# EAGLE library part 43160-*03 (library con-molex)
SDA-43160 Connector Source: http://www.molex.com/pdm_docs/sd/431601306_sd.pdf
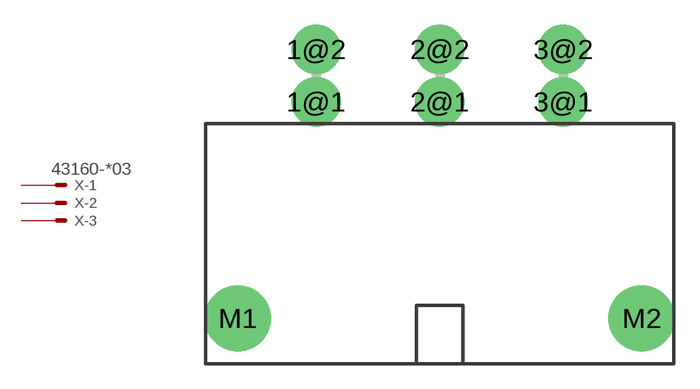
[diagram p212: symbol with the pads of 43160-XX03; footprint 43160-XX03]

Designator prefix X; gates -1=MV2 -2=M2 -3=M2

## 43160-1103 (OC_FARNELL: unknown; OC_NEWARK: unknown), 43160-1203 (OC_FARNELL: unknown; OC_NEWARK: unknown), 43160-1303 (MPN: 43160-1303; OC_FARNELL: unknown; OC_NEWARK: 92M1481), 43160-1403 (OC_FARNELL: unknown; OC_NEWARK: unknown), 43160-3103 (MF: WALDOM/MOLEX; MPN: 43160-3103; OC_FARNELL: 3293040; OC_NEWARK: 54H0265), 43160-3203 (OC_FARNELL: unknown; OC_NEWARK: unknown), 43160-5103 (MPN: 43160-5103; OC_FARNELL: unknown; OC_NEWARK: 92M1494), 43160-5203 (OC_FARNELL: unknown; OC_NEWARK: unknown), 43160-5303 (MPN: 43160-5303; OC_FARNELL: unknown; OC_NEWARK: 92M1499), 43160-5403 (OC_FARNELL: unknown; OC_NEWARK: unknown), 43160-7303 (MPN: 43160-7303; OC_FARNELL: unknown; OC_NEWARK: 92M1508), 43160-7403 (OC_FARNELL: unknown; OC_NEWARK: unknown)  [43160-XX03]
1@1  -1:S  pas
1@2  -1:S  pas
2@1  -2:S  pas
2@2  -2:S  pas
3@1  -3:S  pas
3@2  -3:S  pas

## Footprint 43160-XX03 (pad centres in mm)
SDA-43160 Connector Source: http://www.molex.com/pdm_docs/sd/431601306_sd.pdf
drill 1.8 pad 3 round: 1@1 -7.49,0; 1@2 -7.49,3.18; 2@1 0,0; 2@2 0,3.18; 3@1 7.49,0; 3@2 7.49,3.18
drill 3 pad 3.4 round: M1 -12.24,-13.13; M2 12.24,-13.13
